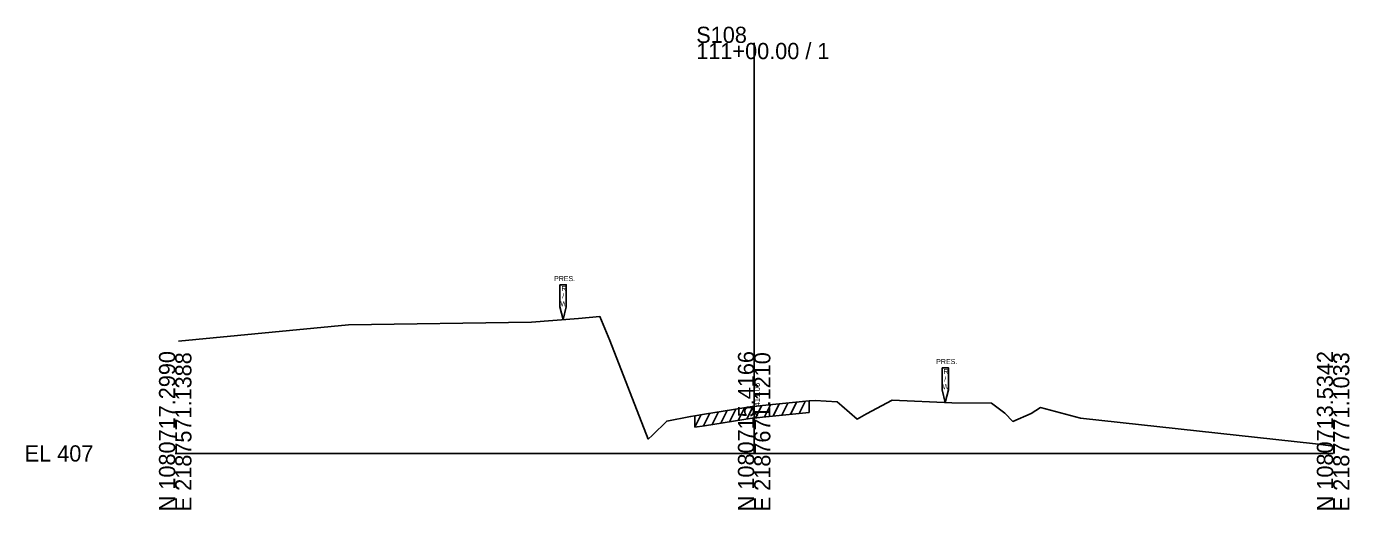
# Model space of a CAD drawing. Extents: x -26 to 2203, y 490 to 19581.
# Drawn here: x -25.7 to 202.8, y 15490.3 to 15573.8 of the extents above; entities that cross this region are included whole.
import ezdxf

# ---------------------------------------------------------------- set-up
doc = ezdxf.new("R2010")
doc.units = 0
for name, color, linetype in [('RD_GPK_XS_Cell', 7, 'Continuous'), ('RD_XS_ExGround', 7, 'Continuous'), ('RD_XS_ExPaveRet', 7, 'Continuous'), ('RD_XS_ExRW', 7, 'Continuous'), ('RD_XS_TX_Elev_EX', 7, 'Continuous')]:
    doc.layers.add(name, color=color, linetype=linetype)

msp = doc.modelspace()

# ---------------------------------------------------------------- linework, layer by layer
at = {"layer": 'RD_GPK_XS_Cell'}
for p, q in [((100, 15500), (100, 15570.92)), ((0, 15500), (100, 15500)), ((100, 15500), (200, 15500))]:
    msp.add_line(p, q, dxfattribs=at)
at = {"layer": 'RD_XS_ExGround'}
msp.add_lwpolyline([(0.59, 15519.4), (29.95, 15522.19), (61.54, 15522.68), (69.66, 15523.34), (73.35, 15523.64), (75.05, 15519.49), (81.72, 15502.48), (82.43, 15503.16), (84.89, 15505.59), (89.03, 15506.38), (89.76, 15506.52), (91.4, 15506.79), (99.63, 15508.09), (100, 15508.12), (101.42, 15508.27), (109.53, 15509.06), (110.52, 15509.12), (114.33, 15508.94), (115.12, 15508.2), (117.8, 15505.94), (119.43, 15506.85), (123.83, 15509.23), (134.13, 15508.75), (141, 15508.68), (143.3, 15506.94), (144.68, 15505.53), (147.83, 15506.89), (149.45, 15507.91), (156.37, 15506.1), (196.96, 15501.64), (200, 15501.24)], dxfattribs=at)
at = {"layer": 'RD_XS_ExPaveRet'}
for p, q in [((100.26, 15506.15), (101.32, 15508.26)), ((101.76, 15506.3), (102.81, 15508.41)), ((103.26, 15506.45), (104.31, 15508.55)), ((104.76, 15506.6), (105.81, 15508.7)), ((106.26, 15506.74), (107.31, 15508.85)), ((107.76, 15506.89), (108.81, 15508.99)), ((109.53, 15509.06), (109.53, 15507.06)), ((89.76, 15504.52), (90.85, 15506.7)), ((89.76, 15504.52), (89.76, 15506.52)), ((91.26, 15504.76), (92.35, 15506.94)), ((91.4, 15504.79), (99.63, 15506.09)), ((92.76, 15505), (93.85, 15507.17)), ((94.26, 15505.24), (95.35, 15507.41)), ((95.76, 15505.48), (96.85, 15507.65)), ((97.26, 15505.71), (98.35, 15507.88)), ((98.76, 15505.95), (99.84, 15508.11)), ((99.63, 15506.09), (100, 15506.12)), ((100, 15506.12), (101.42, 15506.27)), ((101.42, 15506.27), (109.53, 15507.06)), ((89.76, 15504.52), (91.4, 15504.79))]:
    msp.add_line(p, q, dxfattribs=at)
at = {"layer": 'RD_XS_ExRW'}
for points in [[(66.45, 15529.14), (67.55, 15529.14), (67.55, 15525.31), (67, 15523.13), (66.45, 15525.31)], [(132.45, 15514.81), (133.55, 15514.81), (133.55, 15510.99), (133, 15508.8), (132.45, 15510.99)]]:
    msp.add_lwpolyline(points, close=True, dxfattribs=at)

# ---------------------------------------------------------------- texts
at = {"layer": 'RD_GPK_XS_Cell'}
for s, p in [('S108', (90, 15570.92)), ('111+00.00 / 1', (90, 15568.12)), ('EL 407', (-26, 15498.6))]:
    msp.add_text(s, height=2.8, dxfattribs=at).set_placement(p)
for s, p in [('N 1080717.2990', (0, 15490)), ('N 1080715.4166', (100, 15490)), ('N 1080713.5342', (200, 15490)), ('E 2187571.1388', (2.8, 15490)), ('E 2187671.1210', (102.8, 15490)), ('E 2187771.1033', (202.8, 15490))]:
    msp.add_text(s, height=2.8, rotation=90, dxfattribs=at).set_placement(p)
at = {"layer": 'RD_XS_ExRW'}
for s, p in [('PRES.', (65.45, 15529.77)), ('R', (66.71, 15528.05)), ('/', (66.83, 15526.74)), ('W', (66.53, 15525.43)), ('PRES.', (131.45, 15515.44)), ('R', (132.71, 15513.72)), ('/', (132.83, 15512.41)), ('W', (132.53, 15511.1))]:
    msp.add_text(s, height=0.875, dxfattribs=at).set_placement(p)
at = {"layer": 'RD_XS_TX_Elev_EX'}
msp.add_text('411.06', height=1, rotation=90, dxfattribs=at).set_placement((101, 15508.12))

doc.saveas('drawing.dxf')
